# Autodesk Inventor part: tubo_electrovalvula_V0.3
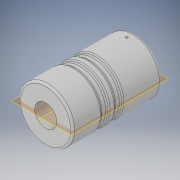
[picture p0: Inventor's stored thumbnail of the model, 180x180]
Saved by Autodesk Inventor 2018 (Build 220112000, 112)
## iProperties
Created: 2018-09
Part Number: tubo_electrovalvula_V0.3
Material: Generic
Document SubType Name: Modeling
Designer: Gordillo
Density: 1 g/cm^3
Appearance: Default
Author: Gordillo
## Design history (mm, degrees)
sketch "Sketch1"
  geometry: C1 r 55 at (0, 0); 1 further point
  constraints: 1 centre point, 1 coincident
  dimensions: "d0" = 110 diameter of C1
extrude "Extrusion1" new body sketch "Sketch1" distance "d1" = 180; taper "d2" = 0 deg
sketch "Sketch2"
  geometry: L1 (55, 180)-(-55, 180) reference; L2 (-55, 0)-(55, 0) reference; L3 (55, 0)-(55, 180) reference; L4 (55, 80)-(52, 80); L5 (52, 80)-(52, 92); L6 (52, 92)-(55, 92); L7 (55, 92)-(55, 80); L8 (55, 108)-(52, 108); L9 (52, 108)-(52, 120); L10 (52, 120)-(55, 120); L11 (55, 120)-(55, 108); L12 (0, -36)-(0, 216) reference; 1 further point
  constraints: 16 end point, 4 parallel, 2 horizontal, 2 perpendicular, 2 point on line
  dimensions: "d3" = 3 distance of L5.end L6.end; "d4" = 12 distance of L4.end L5.end; "d5" = 80 distance between parallel lines of L2 L4; "d6" = 3 distance of L9.end L10.end; "d7" = 12 distance of L8.end L9.end; "d8" = 16 distance between parallel lines of L8 L6
revolve "Revolution1" sketch "Sketch2" stored, may be unused: angle "d9" = 90 deg
fillet "Fillet1" dims "d10" = 4
sketch "Sketch3"
  geometry: C1 r 22.5 at (0, 0); 1 further point
  constraints: 1 centre point, 1 coincident
  dimensions: "d11" = 45 diameter of C1
extrude "Extrusion2" cut sketch "Sketch3" distance "d12" = 150; taper "d13" = 0 deg
fillet "Fillet2" dims "d14" = 4
workplane "Work Plane1"
sketch "Sketch4"
  geometry: L1 (0, -36)-(0, 216) reference; L2 (51, 0)-(-51, 0) reference; 2 further points
  constraints: 1 point on line
  dimensions: "d15" = 45 distance from line of L2 point (0, 45)
hole "Hole1" sketch "Sketch4" at (0, 45) diameter "d16" = 12; stored, may be unused: countersink angle "d20" = 90 deg, drill point angle "d22" = 118 deg; dims "d17" = 6, "d18" = 14, "d19" = 4, "d21" = 8
thread "Thread1" dims "d23" = 10, "d24" = 0
sketch "Sketch5"
  geometry: L1 (-55, 4)-(55, 4) reference; L2 (51, 0)-(-51, 0) reference; L3 (-55, 4)-(-55, 76.127) reference; L4 (55, 4)-(55, 76.127) reference; L5 (0, -36.994)-(0, 216.166) reference; C1 r 2 at (0, 15); A1 r 4 centre (51, 4) between (51, 0) and (55, 4) reference; A2 r 4 centre (-51, 4) between (-55, 4) and (-51, 0) reference; 1 further point
  constraints: 1 centre point, 1 point on line
  dimensions: "d25" = 4 diameter of C1; "d26" = 15 distance from line of L2 C1.centre
extrude "Extrusion3" cut sketch "Sketch5" extent not by distance; stored distance "d27" = 200; taper "d28" = 0 deg
body "Solid1"
node "Projected Loop1"
node "Projected Loop2"
